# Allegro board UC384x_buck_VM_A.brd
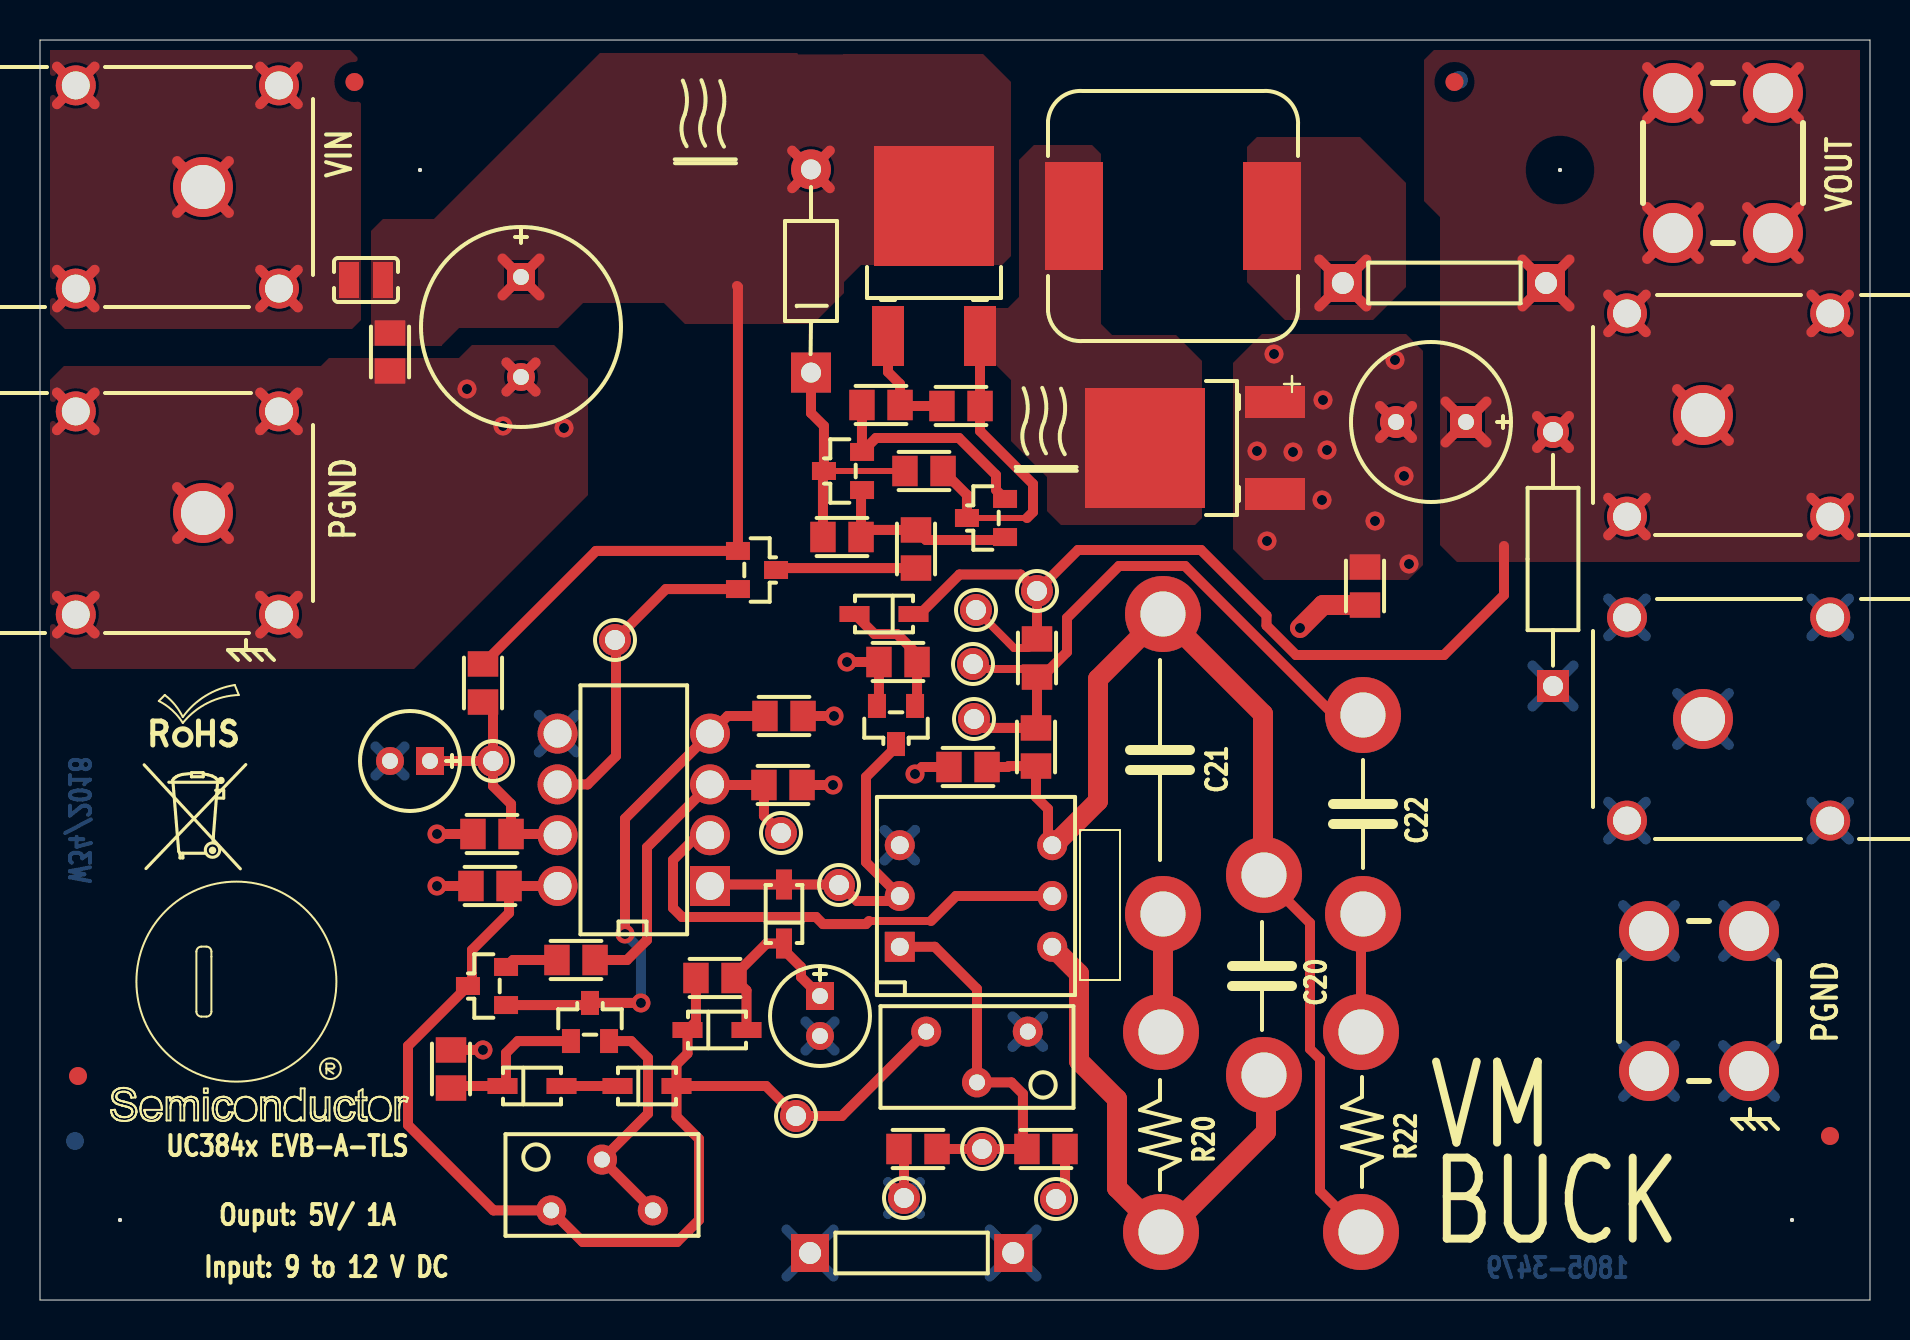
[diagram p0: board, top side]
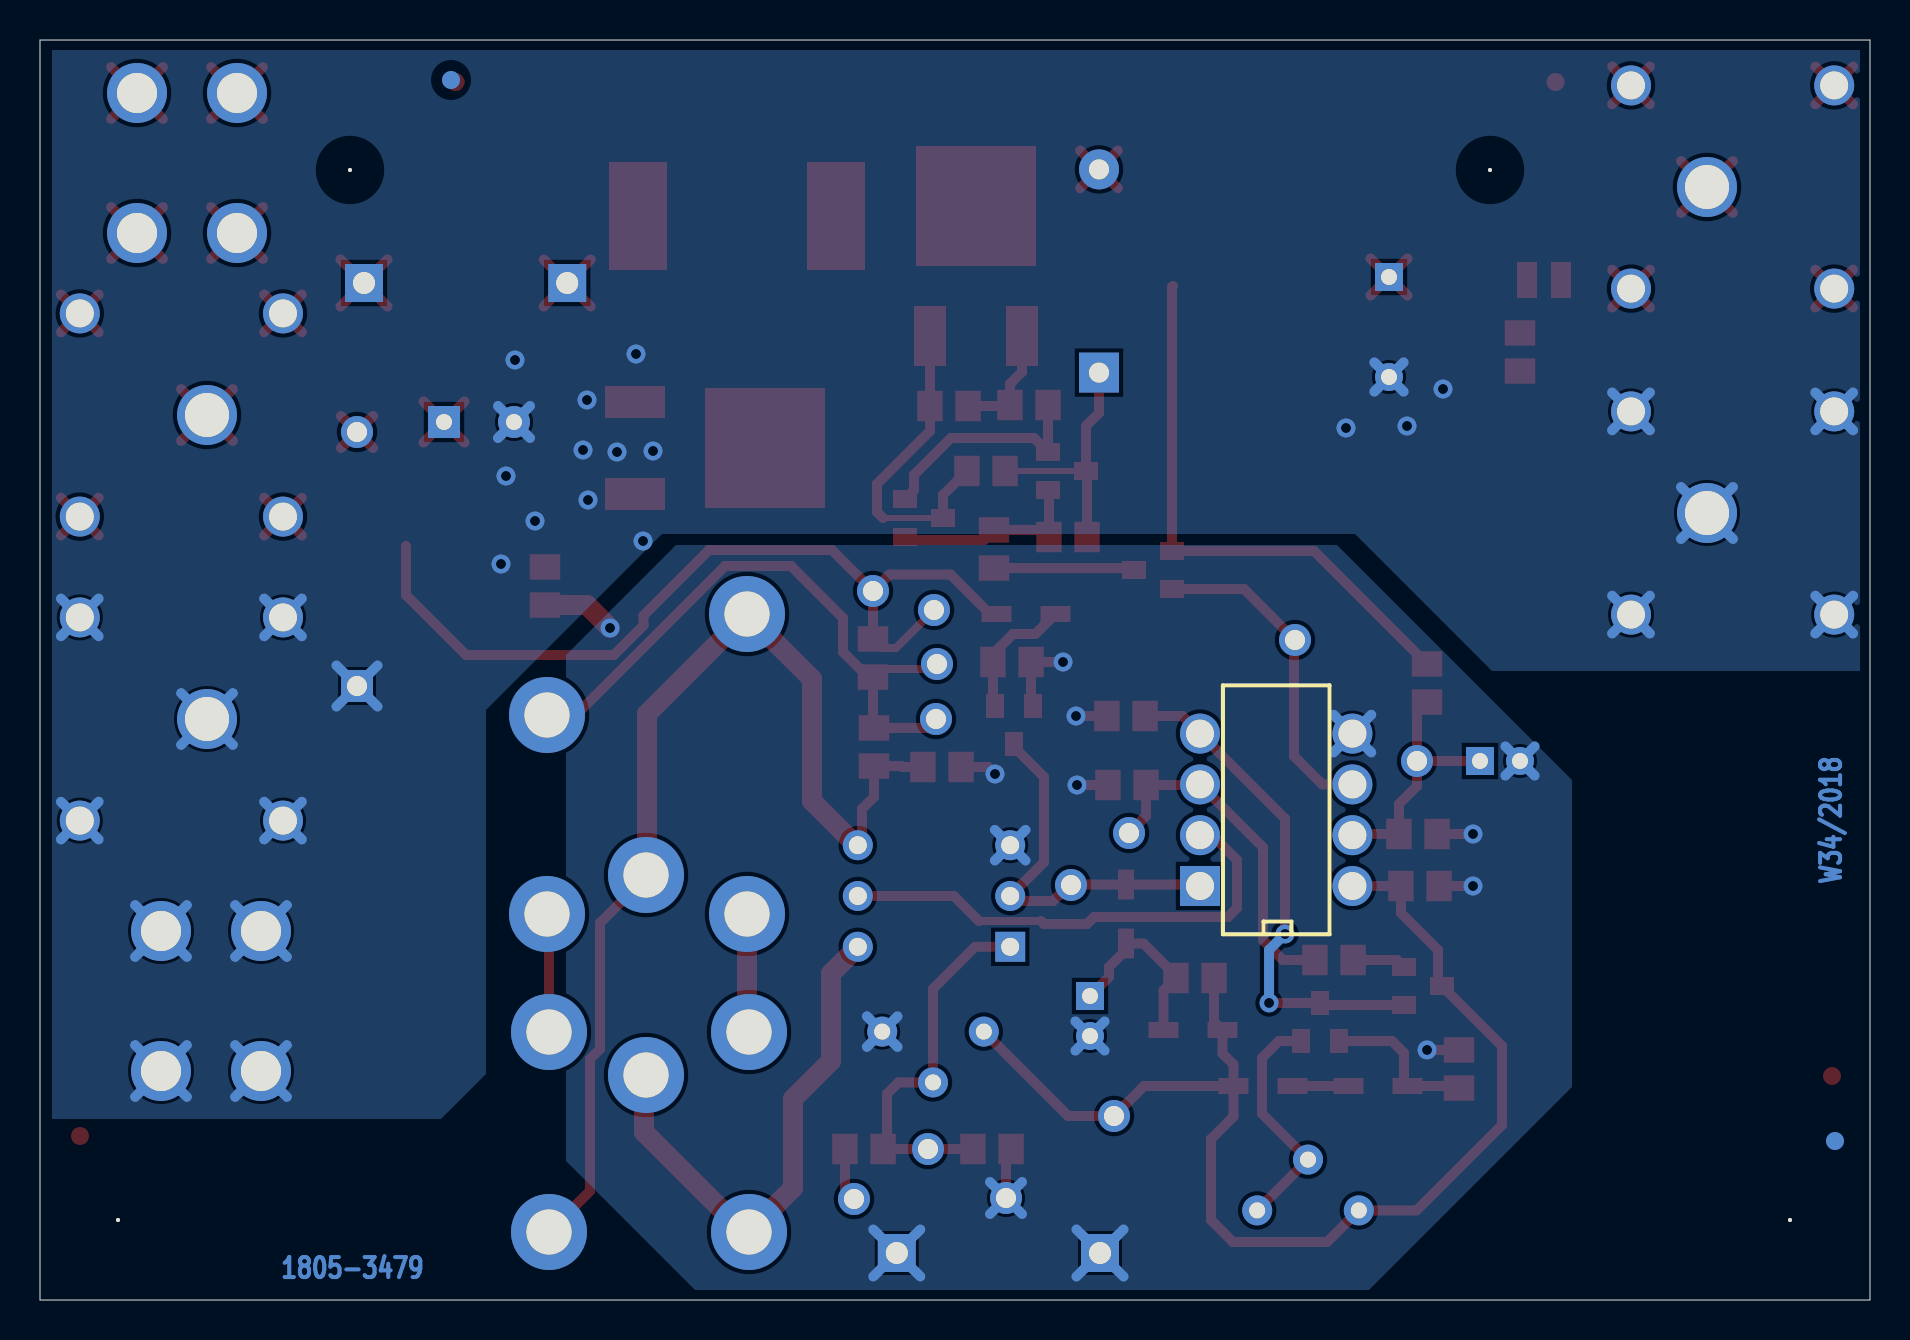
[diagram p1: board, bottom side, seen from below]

Outline 91.5 x 63 mm; copper layers: TOP, BOTTOM. Coordinates in mm from the lower left corner of the outline.
Outline path: 0,63 0,0 91.5,0 91.5,63 0,63

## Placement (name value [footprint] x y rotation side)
ACM_H  TEST POINT  [TP]  50.8 5.05 180 top
ACM_L  TEST POINT  [TP]  43.2 5.1 180 top
C1  100nF  [0805]  22.5 20.7 180 top
C3  2.2uF  [CAPA_CH_D5_H11_P2]  18.5 26.95 180 top
C4  220uF  [CAPA_CH_D8_H12_P3V5]  69.55 43.9 180 top
C5  470uF  [CAPA_CH_D10_H13_P5]  24.05 48.65 270 top
C6  1uF  [0805]  17.5 47.4 270 top
C7  100nF  [0805]  22.6 23.3 180 top
C8  100nF  [0805]  43.9 7.55 0 top
C9  2.2uF  [0805]  50.3 7.55 180 top
C10  0.1uF  [0805]  44.2 41.45 0 top
C12  100uF /6v3  [CAPA_CH_D5_H11_P2]  39 14.2 270 top
CB1  target_cms  [MIRE_LOW]  1.75 7.95 180 bottom
CB2  target_cms  [MIRE_LOW]  70.95 61 180 bottom
CB3  target_cms  [MIRE_LOW]  1.9 11.2 0 top
CB4  target_cms  [MIRE_LOW]  70.72 60.9 0 top
CB5  target_cms  [MIRE_LOW]  89.5 8.2 0 top
CB6  target_cms  [MIRE_LOW]  15.72 60.9 0 top
COMP  TEST POINT  [TP]  39.95 20.75 180 top
CT  1nF  [0805]  37.2 29.2 0 top
D1  1N4148w  [SOD123]  30.35 10.7 0 top
D2  1N4148w  [SOD123]  24.6 10.7 0 top
D3  MBRD1045T4G  [DPAK_TO252]  56.85 42.6 90 top
D4  1N4148w  [SOD123]  33.85 13.5 0 top
D5  1N4148w  [SOD123]  37.2 19.3 90 top
D6  MMSZ6V2T1G  [SOD123]  42.2 34.3 180 top
D7  1N5817  [DO41]  38.55 51.45 90 top
DRV  TEST POINT  [TP]  28.75 33 180 top
J1A  SLB4-I/90_R  [BANANE_4MM_SLB4]  8.15 55.65 180 top
J1B  SLB4-I/90_B  [BANANE_4MM_SLB4]  8.15 39.35 180 top
J1C  SLB4-I/90_R  [BANANE_4MM_SLB4]  83.15 44.25 0 top
J1D  SLB4-I/90_B  [BANANE_4MM_SLB4]  83.15 29.05 0 top
J2A  Screw_terminal  [PC_7701]  84.15 56.85 0 top
J2B  Screw_terminal  [PC_7701]  82.95 14.95 0 top
L1  100uH-1.7A  [SELF_WE-PD-1260]  56.65 54.2 90 top
L2  2.2uH  [SELF_SRN2009]  16.3 51 0 top
NOREF  -  []  91.5 0 90 top
NOREF#2  -  []  87.6 4 0 top
NOREF#3  -  [unnamed#2]  4 4 0 top
NOREF#4  -  []  0 63 0 top
NOREF#5  -  []  91.5 0 90 top
NOREF#6  -  []  -114.15 -47.45 0 top
NOREF#7  -  []  -181.6 -74.35 0 top
NOREF#8  -  [unnamed#2]  76 56.5 0 top
NOREF#9  -  [unnamed#2]  87.6 4 0 top
NOREF#10  -  [unnamed#2]  19 56.5 0 top
NOREF#11  -  []  283.55 -63.75 180 bottom
P1  10K  [POTAR_12T_3266W]  46.85 12.15 180 top
P2  10K  [POTAR_12T_3266W]  28.1 5.75 0 top
PC5  D  [PLOT_5380598-2]  61.2 21.25 0 top
PC6  D  [PLOT_5380598-2]  61.2 11.25 0 top
PC7  D  [PLOT_5380598-2]  56.15 34.3 0 top
PC8  D  [PLOT_5380598-2]  56.15 19.3 0 top
PC9  D  [PLOT_5380598-2]  56.05 13.4 0 top
PC10  D  [PLOT_5380598-2]  56.05 3.4 0 top
PC11  D  [PLOT_5380598-2]  66.05 3.4 0 top
PC12  D  [PLOT_5380598-2]  66.15 19.3 0 top
PC13  D  [PLOT_5380598-2]  66.05 13.4 0 top
PC14  D  [PLOT_5380598-2]  66.15 29.25 0 top
Q1  NTD5865NLT4G  [DPAK_TO252]  44.7 53.1 0 top
Q2  MMBT2907A  [SOT23]  27.5 13.9 180 top
Q3  MMBT2222A  [SOT23]  22.35 15.7 270 top
Q4  MMBT2222A  [SOT23]  42.8 28.75 0 top
Q5  MMBT2222A  [SOT23]  40.15 41.45 270 top
Q6  MMBT2907A  [SOT23]  47.3 39.1 270 top
Q7  BSS138LT1G  [SOT23]  35.85 36.5 90 top
R1  10K  [0805]  49.8 27.65 90 top
R2  10K  [0805]  20.55 11.55 270 top
R3  1K  [0805]  37.15 25.75 180 top
R4  2.7K  [0805]  26.8 17 180 top
R5  10R  [0805]  22.15 30.85 90 top
R6  47K  [0805]  46.05 44.7 180 top
R7  10K  [0805]  46.4 26.65 0 top
R8  10R  [0805]  49.85 32.1 90 top
R9  10R  [0805]  42.05 44.75 0 top
R10  0R  [0805]  66.25 35.7 90 top
R11  1K / 0.5W  [RC21U]  75.65 37.05 90 top
R12  2.2K  [0805]  40.1 38.15 0 top
R13  1.5K  [0805]  33.75 16.1 180 top
R14  1K  [0805]  42.9 31.9 0 top
R15  100  [0805]  43.8 37.55 270 top
S1  Strap  [JUMPER400H]  75.3 50.85 180 top
S2  Strap  [JUMPER400H]  38.5 2.35 0 top
SAW  TEST POINT  [TP]  37.05 23.35 0 top
SW1  DPDT  [SW_76SD01ST]  46.8 20.2 0 top
U1  UC3843B  [DIP8_SUP]  33.5 20.7 180 top
VA  TEST POINT  [TP]  46.7 29.05 0 top
VA.  TEST POINT  [TP]  46.65 31.8 0 top
VB  TEST POINT  [TP]  49.85 35.45 0 top
VB.  TEST POINT  [TP]  46.8 34.5 0 top
VCC  TEST POINT  [TP]  22.65 26.95 180 top
VREF  TEST POINT  [TP]  37.8 9.2 0 top
VSET  TEST POINT  [TP]  47.1 7.55 180 top

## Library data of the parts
ACM_H ACM_L COMP DRV S1 S2 SAW VA VA. VB VB. VCC VREF VSET = TEST POINT_0
C1 C6-C10 CT = C
C3 C12 = CAP POL
C4 C5 = C_elect_0
CB1-CB6 = target_cms
D1 D2 D4 D5 = D1N4148_2
D3 = dual_diodeAAK
D6 = DIODE SCHOTTKY_0
D7 = 1N5817_0
J1A J1B J1C J1D = HEADER 1_0
J2A J2B = 4 HEADER_0
L1 = CHOKE
L2 = L
P1 P2 = RESISTOR VAR
PC5-PC14 = T POINT R_0
Q1 = NMOS_2
Q2 Q6 = 2N2907A_0
Q3-Q5 = 2N2222A_0
Q7 = NMOS_1
R1-R15 = R
SW1 = SW DPDT/SM_0
U1 = UC3845B

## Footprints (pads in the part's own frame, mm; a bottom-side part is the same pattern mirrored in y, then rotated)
0805
  rect 1.27x1.524 smd: 1(-0.953,0) 2(0.953,0)
BANANE_4MM_SLB4
  round 3 hole 2.2: 1(0,0)
  round 2 hole 1.4: 2(-3.8,5.08) 3(-3.8,-5.08) 4(6.36,5.08) 5(6.36,-5.08)
CAPA_CH_D5_H11_P2
  rect 1.4x1.4 hole 0.8: 1(-1,0)
  round 1.4 hole 0.8: 2(1,0)
CAPA_CH_D8_H12_P3V5
  rect 1.6x1.6 hole 0.8: 1(-1.75,0)
  round 1.6 hole 0.8: 2(1.75,0)
CAPA_CH_D10_H13_P5
  rect 1.4x1.4 hole 0.8: 1(-2.5,0)
  round 1.4 hole 0.8: 2(2.5,0)
DIP8_SUP
  rect 2x2 hole 1.4: 1(0,0)
  round 2 hole 1.4: 2(0,-2.54) 3(0,-5.08) 4(0,-7.62) 5(7.62,-7.62) 6(7.62,-5.08) 7(7.62,-2.54) 8(7.62,0)
DO41
  rect 2x2 hole 1: 1(-5.08,0)
  round 2 hole 1: 2(5.08,0)
DPAK_TO252
  rect 1.6x3 smd: 1(-2.3,-4.9) 3(2.3,-4.9)
  rect 6x6 smd: 2(0,1.6)
JUMPER400H
  rect 1.9x1.9 hole 1.1: 1(0,0) 2(10.16,0)
MIRE_LOW
  round 0.9 smd: 1(0,0)
PC_7701
  round 3 hole 2: 1(-2.5,-3.5) 2(2.5,-3.5) 3(2.5,3.5) 4(-2.5,3.5)
PLOT_5380598-2
  round 3.8 hole 2.25: 1(0,0)
POTAR_12T_3266W
  round 1.5 hole 0.8: 1(-2.54,-1.27) 2(0,1.27) 3(2.54,-1.27)
RC21U
  rect 1.6x1.6 hole 1: 1(-6.35,0)
  round 1.6 hole 1: 2(6.35,0)
SELF_SRN2009
  rect 1x1.8 smd: 1(-0.85,0) 2(0.85,0)
SELF_WE-PD-1260
  rect 5.4x2.9 smd: 1(0,4.95) 2(0,-4.95)
SOD123
  rect 1.5x0.8 smd: 1(-1.475,0) 2(1.475,0)
SOT23
  rect 0.9x1.2 smd: 1(0.953,0.953) 2(-0.953,0.953) 3(0,-0.953)
SW_76SD01ST
  rect 1.5x1.5 hole 0.9: 1(-3.81,-2.54)
  round 1.5 hole 0.9: 2(-3.81,2.54) 11(3.81,-2.54) 22(3.81,2.54) C1(-3.81,0) C2(3.81,0)
TP
  round 1.6 hole 1: 1(0,0)
unnamed#2
  round 0.2 hole 3 unplated: (0,0)

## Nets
GND_EARTH: ACM_L.1 C1.2 C3.2 C7.2 C8.1 C12.2 CT.2 P1.1(A) Q4.2(EMITTER) R2.1 R3.1 R7.1 R10.1 R14.1 S2.1 S2.2 SW1.2(NO2) U1.5(GND)
GND_SIGNAL: C4.2(-) C5.2(-) C6.2 D3.1(A1) D3.3(A2) J1B.1 J1B.2 J1B.3 J1B.4 J1B.5 J1D.1 J1D.2 J1D.3 J1D.4 J1D.5 J2B.1 J2B.2 J2B.3 J2B.4 R10.2 R11.1
VCC: C3.1 C7.1 R5.1 U1.7(VCC) VCC.1
CMP: COMP.1 D5.2 Q4.3(COLLECTOR) SW1.C1(COMMON1) U1.1(EA)
DRV: DRV.1 Q7.2(S) U1.6(DRV)
REF: C1.1 D1.2 D4.1 P1.3(B) P2.1(A) Q3.3(COLLECTOR) R13.2 U1.8(REF) VREF.1
VOUT: C4.1(+) D6.1(CATHODE) J1C.1 J1C.2 J1C.3 J1C.4 J1C.5 J2A.1 J2A.2 J2A.3 J2A.4 R8.2 R11.2 S1.1 VB.1 VB..1
N12289703: C5.1(+) C6.1 D7.2 L2.2 Q1.2(D) Q7.1(G) R5.2
N12295469: CT.1 Q2.3(COLLECTOR) Q3.1(BASE) U1.4(RT/CT)
N12295845: R3.2 R4.1 SAW.1 U1.3(IS)
N12298127: PC5.1(TP) PC7.1(TP) PC11.1(TP) R1.1 R7.2 SW1.22(NC2)
N12299817: PC8.1(TP) PC9.1(TP)
N12299821: PC6.1(TP) PC10.1(TP) SW1.11(NC1)
N12517793: J1A.1 J1A.2 J1A.3 J1A.4 J1A.5 L2.1
N12518780: Q7.3(D) R15.2
N12519598: Q5.1(BASE) Q6.1(BASE) R12.2 R15.1
N12520738: C10.1 D7.1 Q5.3(COLLECTOR) R12.1
N12521657: Q5.2(EMITTER) Q6.2(EMITTER) R9.1
N12521671: Q1.1(G) R6.2 R9.2
N12521759: C10.2 D3.2(C) L1.1 Q1.3(S) Q6.3(COLLECTOR) R6.1
N12522225: L1.2 S1.2
N12524308: C12.1 D4.2 D5.1 R13.1
N12524599: D6.2(ANODE) Q4.1(BASE) R14.2
N12543157: PC12.1(TP) PC13.1(TP)
N12543161: PC14.1(TP) R1.2 R8.1 VA.1 VA..1
N12544501: ACM_H.1 C9.1
N12544892: C8.2 C9.2 P1.2(WIPER) SW1.1(NO1) VSET.1
N12545642: SW1.C2(COMMON2) U1.2(FB)
N12547004: Q3.2(EMITTER) R4.2
N12548180: P2.2(WIPER) P2.3(B) Q2.2(EMITTER)
N12548483: D2.1 Q2.1(BASE) R2.2
N12548948: D1.1 D2.2

Pads without a net: CB1 1; CB2 1; CB3 1; CB4 1; CB5 1; CB6 1

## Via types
v1: diameter 0.95, hole 0.5, TOP to BOTTOM, 24 vias

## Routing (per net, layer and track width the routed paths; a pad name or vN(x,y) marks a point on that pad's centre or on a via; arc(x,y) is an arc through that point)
GND_EARTH: length 61
  TOP w0.5: v1(43.75,26.3) 44.1,26.65 R7.1 ; Q4.2 41.95,29.8 R14.1 ; 41.85,31.8 R14.1 ; R14.1 v1(40.35,31.9) ; CT.2 v1(39.7,29.2) ; 42.7,5.6 ACM_L.1 43.2,7.3 C8.1 ; C7.2 v1(19.85,23.3) ; C1.2 v1(19.85,20.7) ; R2.1 v1(22.15,12.5) ; R3.1 v1(39.65,25.75)
  TOP w1: v1(63,33.6) 64.15,34.75 66.25,34.75 R10.1
  BOTTOM w0.5: 38.27,12.47 C12.2 ; C12.2 39.73,13.93 ; C12.2 38.27,13.93 ; C12.2 39.73,12.47 ; S2.1 39.68,1.17 ; S2.1 39.68,3.53 ; S2.1 37.32,1.17 ; S2.1 37.32,3.53 ; 16.77,26.22 C3.2 ; C3.2 16.77,27.68 ; C3.2 18.23,27.68 ; C3.2 18.23,26.22 ; 47.48,3.53 S2.2 ; S2.2 47.48,1.17 ; S2.2 49.84,3.53 ; S2.2 49.84,1.17 ; SW1.2 43.75,23.5 ; SW1.2 42.23,21.98 ; SW1.2 43.75,21.98 ; SW1.2 42.23,23.5 ; U1.5 26.82,29.26 ; U1.5 26.82,27.38 ; U1.5 24.94,27.38 ; U1.5 24.94,29.26 ; 42.4,4.3 ACM_L.1 ; ACM_L.1 44,5.9 ; ACM_L.1 42.4,5.9 ; ACM_L.1 44,4.3 ; P1.1 50.15,12.66 ; P1.1 48.63,14.18 ; P1.1 48.63,12.66 ; P1.1 50.15,14.18
GND_SIGNAL: length 138.3
  TOP w0.5: 11.01,33.33 J1B.2 ; J1B.2 12.89,33.33 ; J1B.2 12.89,35.21 ; J1B.2 11.01,35.21 ; J1B.5 2.73,45.37 ; J1B.5 0.85,43.49 ; J1B.5 0.85,45.37 ; J1B.5 2.73,43.49 ; J1B.4 2.73,35.21 ; J1B.4 0.85,35.21 ; J1B.4 0.85,33.33 ; J1B.4 2.73,33.33 ; C4.2 68.6,44.7 ; C4.2 68.6,43.1 ; C4.2 67,44.7 ; C4.2 67,43.1 ; 11.01,45.37 J1B.3 ; J1B.3 12.89,43.49 ; J1B.3 12.89,45.37 ; J1B.3 11.01,43.49 ; C5.2 24.78,46.88 ; C5.2 23.32,45.42 ; C5.2 24.78,45.42 ; C5.2 23.32,46.88 ; J1B.1 9.44,40.64 ; J1B.1 9.44,38.06 ; J1B.1 6.86,38.06 ; J1B.1 6.86,40.64
  BOTTOM w0.5: 0.85,33.33 J1B.4 ; J1B.4 0.85,35.21 ; J1B.4 2.73,33.33 ; J1B.4 2.73,35.21 ; 23.32,45.42 C5.2 ; C5.2 23.32,46.88 ; C5.2 24.78,45.42 ; C5.2 24.78,46.88 ; J1D.5 90.45,24.91 ; J1D.5 90.45,23.03 ; J1D.5 88.57,24.91 ; J1D.5 88.57,23.03 ; 84.16,10.16 J2B.2 ; J2B.2 86.74,10.16 ; J2B.2 86.74,12.74 ; J2B.2 84.16,12.74 ; 81.86,30.34 J1D.1 ; J1D.1 84.44,30.34 ; J1D.1 81.86,27.76 ; J1D.1 84.44,27.76 ; 6.86,40.64 J1B.1 ; J1B.1 6.86,38.06 ; J1B.1 9.44,40.64 ; J1B.1 9.44,38.06 ; 11.01,33.33 J1B.2 ; J1B.2 12.89,33.33 ; J1B.2 12.89,35.21 ; J1B.2 11.01,35.21 ; J1B.3 12.89,43.49 ; J1B.3 11.01,45.37 ; J1B.3 11.01,43.49 ; J1B.3 12.89,45.37 ; R11.1 76.68,29.67 ; R11.1 74.62,31.73 ; R11.1 76.68,31.73 ; R11.1 74.62,29.67 ; 78.41,24.91 J1D.3 ; J1D.3 78.41,23.03 ; J1D.3 80.29,24.91 ; J1D.3 80.29,23.03 ; J1D.4 90.45,35.07 ; J1D.4 88.57,35.07 ; J1D.4 90.45,33.19 ; J1D.4 88.57,33.19 ; C4.2 68.6,44.7 ; C4.2 67,43.1 ; C4.2 67,44.7 ; C4.2 68.6,43.1 ; 78.41,33.19 J1D.2 ; J1D.2 80.29,35.07 ; J1D.2 80.29,33.19 ; J1D.2 78.41,35.07 ; 0.85,45.37 J1B.5 ; J1B.5 2.73,43.49 ; J1B.5 0.85,43.49 ; J1B.5 2.73,45.37 ; J2B.3 86.74,17.16 ; J2B.3 84.16,17.16 ; J2B.3 84.16,19.74 ; J2B.3 86.74,19.74 ; J2B.4 81.74,17.16 ; J2B.4 79.16,19.74 ; J2B.4 81.74,19.74 ; J2B.4 79.16,17.16 ; 79.16,12.74 J2B.1 ; J2B.1 79.16,10.16 ; J2B.1 81.74,12.74 ; J2B.1 81.74,10.16
  vias: v1(21.35,45.55) v1(23.15,43.7) v1(26.2,43.6) v1(60.85,42.45) v1(61.35,37.95) v1(61.7,47.3) v1(62.65,42.4) v1(64.1,40) v1(64.15,45) v1(64.35,42.5) v1(66.75,38.95) v1(67.75,47) v1(68.2,41.2) v1(68.45,36.8)
VCC: length 12.7
  TOP w0.5: U1.7 25.82,23.3 C7.1 23.55,24.8 22.65,25.7 VCC.1 ; VCC.1 C3.1 ; VCC.1 22.65,29.4 R5.1
CMP: length 18.9
  TOP w0.5: Q4.3 42.8,27.65 41.3,26.15 41.3,21.89 SW1.C1 42.74,19.95 40.85,19.95 40.05,20.75 COMP.1 39.92,20.77 D5.2 33.58,20.77 U1.1
DRV: length 16.5
  TOP w0.5: Q7.2 31.3,35.55 DRV.1 28.8,32.95 28.8,27.2 27.38,25.78 U1.6
REF: length 61.7
  TOP w0.5: U1.8 C1.1 23.45,19.35 21.6,17.5 21.6,15.9 Q3.3 18.4,12.7 18.4,8.75 22.67,4.48 P2.1 27.14,2.9 31.85,2.9 32.95,4 32.95,8.05 31.82,9.18 31.82,10.7 ; 31.82,10.7 31.82,11.78 32.38,12.32 D4.1 32.8,13.92 R13.2 ; 31.82,10.7 36.3,10.7 VREF.1 40.09,9.2 P1.3
VOUT: length 119.1
  TOP w0.3: R8.2 49.8,33.05
  TOP w0.4: R8.2 49.4,32.6 48.7,32.6 VB..1
  TOP w0.5: R11.2 76.45,42.6 ; R11.2 76.45,44.2 ; R11.2 74.85,42.6 ; R11.2 74.85,44.2 ; J2A.3 87.94,61.64 ; J2A.3 85.36,61.64 ; J2A.3 87.94,59.06 ; J2A.3 85.36,59.06 ; 88.57,48.39 J1C.4 ; J1C.4 88.57,50.27 ; J1C.4 90.45,48.39 ; J1C.4 90.45,50.27 ; 70.27,44.93 C4.1 ; C4.1 72.33,42.87 ; C4.1 72.33,44.93 ; C4.1 70.27,42.87 ; 80.36,52.06 J2A.1 ; J2A.1 82.94,52.06 ; J2A.1 82.94,54.64 ; J2A.1 80.36,54.64 ; 85.36,52.06 J2A.2 ; J2A.2 85.36,54.64 ; J2A.2 87.94,52.06 ; J2A.2 87.94,54.64 ; 78.41,48.39 J1C.2 ; J1C.2 80.29,48.39 ; J1C.2 80.29,50.27 ; J1C.2 78.41,50.27 ; 78.41,40.11 J1C.3 ; J1C.3 80.29,40.11 ; J1C.3 80.29,38.23 ; J1C.3 78.41,38.23 ; 74.12,49.67 S1.1 ; S1.1 76.48,49.67 ; S1.1 76.48,52.03 ; S1.1 74.12,52.03 ; 88.57,38.23 J1C.5 ; J1C.5 90.45,40.11 ; J1C.5 88.57,40.11 ; J1C.5 90.45,38.23 ; VB.1 R8.2 ; VB.1 49.02,36.27 45.98,36.27 44,34.3 D6.1 ; VB.1 51.9,37.5 58.05,37.5 61.33,34.23 61.33,33.73 62.8,32.25 70.2,32.25 73.2,35.25 73.2,37.7 ; 80.36,61.64 J2A.4 ; J2A.4 82.94,61.64 ; J2A.4 80.36,59.06 ; J2A.4 82.94,59.06 ; J1C.1 84.44,45.54 ; J1C.1 81.86,45.54 ; J1C.1 84.44,42.96 ; J1C.1 81.86,42.96
N12289703: length 38.9
  TOP w0.5: R5.2 27.8,37.45 Q7.1 34.9,50.65 34.85,50.7 ; 23.12,50.22 C5.1 ; C5.1 24.98,52.08 ; C5.1 24.98,50.22 ; C5.1 23.12,52.08 ; D7.2 39.49,55.59 ; D7.2 39.49,57.47 ; D7.2 37.61,55.59 ; D7.2 37.61,57.47
N12295469: length 25.5
  TOP w0.5: Q3.1 27.39,14.75 Q2.3 v1(30.05,14.85) ; CT.1 34.38,29.2 U1.4 29.25,24.07 v1(29.25,18.3)
  BOTTOM w0.5: v1(29.25,18.3) 30.05,17.5 v1(30.05,14.85)
N12295845: length 17.6
  TOP w0.5: SAW.1 36.2,24.2 R3.2 33.53,25.75 U1.3 30.35,22.63 30.35,18 29.35,17 R4.1
N12298127: length 55.7
  TOP w0.5: PC11.1 64,5.45 64,12.05 63.5,12.55 63.5,18.85 61.2,21.15 PC5.1 ; R7.2 48.39,26.65 48.44,26.7 R1.1 49.8,25.15 50.4,24.55 50.4,22.95 SW1.22
  TOP w1: SW1.22 50.69,22.74 52.9,24.95 52.9,31.05 PC7.1 61.15,29.3 61.15,21.3 PC5.1
N12299817: length 5.9
  TOP w1: PC8.1 56.15,13.5 PC9.1
N12299821: length 26.9
  TOP w1: SW1.11 51.95,16.32 51.95,11.95 53.85,10.05 53.85,5.6 PC10.1 56.15,3.3 56.2,3.3 61.3,8.4 61.3,11.15 PC6.1 61.15,11.3
N12517793: length 28.6
  TOP w0.5: J1A.4 2.73,49.63 ; J1A.4 2.73,51.51 ; J1A.4 0.85,49.63 ; J1A.4 0.85,51.51 ; J1A.3 12.89,59.79 ; J1A.3 12.89,61.67 ; J1A.3 11.01,61.67 ; J1A.3 11.01,59.79 ; J1A.5 2.73,59.79 ; J1A.5 2.73,61.67 ; J1A.5 0.85,59.79 ; J1A.5 0.85,61.67 ; 11.01,49.63 J1A.2 ; J1A.2 12.89,51.51 ; J1A.2 12.89,49.63 ; J1A.2 11.01,51.51 ; J1A.1 9.44,54.36 ; J1A.1 6.86,56.94 ; J1A.1 9.44,56.94 ; J1A.1 6.86,54.36
N12518780: length 7
  TOP w0.5: R15.2 36.9,36.6 Q7.3
N12519598: length 10
  TOP w0.5: 41.1,40.55 Q5.1 41.05,40.45 R12.2 41.41,38.5 R15.1 44.3,38 48.1,38 Q6.1
N12520738: length 12.6
  TOP w0.3: Q5.3 C10.1
  TOP w0.5: D7.1 38.55,44.35 39.2,43.7 Q5.3 39.15,41.4 R12.1
N12521657: length 11.5
  TOP w0.5: R9.1 41.1,42.41 Q5.2 41.8,43.1 45.95,43.1 47.8,41.25 47.8,40.51 Q6.2
N12521671: length 5.8
  TOP w0.5: Q1.1 42.4,46.4 43,45.8 R9.2 43,44.7 R6.2
N12521759: length 16.2
  TOP w0.3: Q6.3 49.35,39.1
  TOP w0.5: 49.35,39.1 49.65,39.4 49.65,40.8 47,43.45 R6.1 47,44.7 Q1.3 ; C10.2 46.35,40.26 Q6.3
N12522225: length 6.6
  TOP w0.5: S1.2 66.32,49.67 ; S1.2 63.96,52.03 ; S1.2 63.96,49.67 ; S1.2 66.32,52.03
N12524308: length 9.5
  TOP w0.5: D4.2 35.33,15.48 R13.1 34.7,16.2 36.33,17.82 D5.1 37.2,17.5 38.05,16.65 38.05,16.15 C12.1
N12524599: length 6.7
  TOP w0.5: R14.2 43.85,32.3 42.85,33.3 41.73,33.3 D6.2 ; R14.2 43.75,31.8 ; R14.2 43.85,29.8 Q4.1
N12543157: length 5.9
  TOP w0.5: PC12.1 66.05,19.2 PC13.1
N12543161: length 32
  TOP w0.4: VA..1 46.9,31.55 49.35,31.55 49.75,31.15 R8.1
  TOP w0.5: VA.1 47.15,28.6 R1.2 49.85,28.65 R8.1 50.1,31.15 51.35,32.4 51.35,34.1 53.95,36.7 57.25,36.7 64.7,29.25 PC14.1
N12544501: length 2.7
  TOP w0.5: C9.1 51.25,5.5 ACM_H.1
N12544892: length 19.3
  TOP w0.5: 49.39,7.59 C9.2 ; C9.2 49.15,7.75 49.15,10.3 48.57,10.88 P1.2 46.85,15.55 44.74,17.66 SW1.1 ; C9.2 VSET.1 C8.2
N12545642: length 24.6
  TOP w0.4: 41.45,18.95 44.55,18.95
  TOP w0.5: SW1.C2 45.8,20.2 44.55,18.95 ; 41.45,18.95 41.3,18.8 39.15,18.8 38.8,19.15 32.1,19.15 31.65,19.6 31.65,22 32.89,23.24 U1.2
N12547004: length 2.7
  TOP w0.5: Q3.2 23.65,17 R4.2
N12548180: length 11.9
  TOP w0.5: Q2.2 29.55,12.95 30.4,12.1 30.4,9.32 P2.2 P2.3
N12548483: length 7.8
  TOP w0.5: R2.2 20.65,10.7 D2.1 23.3,10.88 23.3,12.35 23.9,12.95 Q2.1
N12548948: length 2.8
  TOP w0.5: D2.2 D1.1

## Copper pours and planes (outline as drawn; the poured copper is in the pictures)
GND_EARTH on BOTTOM: 25.05,0.5 14.9,10.65 14.9,26 26.65,37.75 59.7,37.75 65.2,32.25 65.2,6.95 58.75,0.5
GND_SIGNAL on TOP: 1.6,31.55 0.5,32.65 0.5,46 1.2,46.7 14.05,46.7 14.45,47.1 20.95,47.1 21.6,47.75 25.7,47.75 27.4,46.05 27.4,40.25 18.7,31.55
GND_SIGNAL on TOP: 69.15,36.75 69.15,47.45 68.3,48.3 61.1,48.3 59.65,46.85 59.65,37.55 61.2,36 68.4,36
GND_SIGNAL on BOTTOM: 71.45,9.05 69.2,11.3 69.2,29.5 60.4,38.3 25.75,38.3 18.9,31.45 0.5,31.45 0.5,62.5 90.9,62.5 90.9,9.05
VOUT on TOP: 70.85,36.9 70,37.75 70,54.15 69.2,54.95 69.2,62 69.7,62.5 91,62.5 91,36.95 90.95,36.9
N12289703 on TOP: 16.55,47.7 16.55,53.45 17.15,54.05 19.7,54.05 28,62.35 37.85,62.35 37.92,62.28 40.12,62.28 40.15,62.3 47.15,62.3 48.55,60.9 48.55,52.2 48.1,51.75 41.05,51.75 40.2,50.9 40.2,50.35 38.65,48.8 32.25,48.8 31.2,49.85 27.15,49.85 25.9,48.6 20.95,48.6 20.1,47.75 20.1,47.7
N12517793 on TOP: 1.25,48.55 0.5,49.3 0.5,62.5 15.5,62.5 16.05,61.95 16.05,49 15.6,48.55
N12521759 on TOP: 46.35,49.6 48.4,49.6 48.95,50.15 48.95,57 49.7,57.75 52.6,57.75 53.05,57.3 53.05,48.8 53.6,48.25 56.8,48.25 58.1,46.95 58.1,39.1 57.75,38.75 51.05,38.75 50.35,39.45 50.35,41.15 48.55,42.95 48.55,46 47.65,46.9 46.5,46.9 46.45,46.85 46.35,46.95
N12522225 on TOP: 60.85,58.15 66,58.15 68.3,55.85 68.3,50.65 66.65,49 62.25,49 60.35,50.9 60.35,57.65

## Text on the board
BOTTOM: BOT 1/1 | 1805-3479 | W34/2018
Ref Des/Silkscreen Bottom: SILK_BOT
User.Comments: VE_BOT | VE_TOP
TOP: TOP 2/2
Ref Des/Silkscreen Top: UC384x EVB-A-TLS | Input: 9 to 12 V DC | Ouput: 5V/ 1A | R20 | C21 | C20 | R22 | C22 | SILK_TOP | VIN | PGND | VOUT | VM | BUCK
DIMENSION: 1.0 | VM BUCK
BODY_CENTER: 1.0
User.5: CHEMICAL NiAu | 35um(1oz)at START | THICKNESS | MATERIAL | STACKUP | FINISH | SILKSCREEN | MINIMAL GAP | MINIMAL SLIVER | BOARD THICKNESS | SOLDER MASK | COPPER THICKNESS | MARKED ON BOTTOM SOLDERMASK | ALL BOARD ELECTRICALLY TESTED | MANUFACTURE 'S LOGO & DATECODE | COMPLIANT RoHS DIRECTIVE 2011/65/UE | DF /2LAYERS | WHITE TOP | FR4 IMPROVED (low CTE) | 210um /8.0mils | GREEN TOP & BOT | 1.6mm /63mils | VIA | 1.0 | VM BUCK | SPEC:
User.6: DEMO UC384x VM BUCK 1805-3479   W34/2018
User.8: FIGURE | SIZE | 0.5 | 0.8 | 0.9 | 1.0 | 1.1 | 1.4 | 2.0 | 2.2 | 2.25 | 3.0 | DRILL CHART: TOP to BOTTOM | ALL UNITS ARE IN MILLIMETERS | TOLERANCE | +0.0/-0.0 | +0.1/-0.05 | +0.05/-0.05 | +0.1/-0.1 | PLATED | NON-PLATED | QTY | 24 | 14 | 6 | 16 | 4 | 8 | 10
